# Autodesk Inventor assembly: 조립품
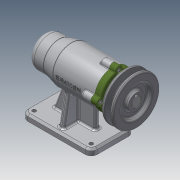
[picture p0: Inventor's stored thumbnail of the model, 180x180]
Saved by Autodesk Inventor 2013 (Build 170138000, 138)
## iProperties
Created: 2019-07
Part Number: 조립품
Document SubType Name: Assembly
Designer: user
Author: user
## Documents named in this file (12)
- C:\Users\user\Desktop\490704V1025\조립품.iam
- C:\Users\user\Desktop\490704V1025\본체.ipt
- C:\Users\user\Desktop\490704V1025\V벨트풀리.ipt
- C:\Users\user\Desktop\490704V1025\멈춤나사 M3.ipt
- C:\Users\user\Desktop\490704V1025\베어링 6004.ipt
- C:\Users\user\Desktop\490704V1025\베어링 51202.ipt
- C:\Users\user\Desktop\490704V1025\볼트 M4.ipt
- C:\Users\user\Desktop\490704V1025\어댑터슬리브.ipt
- C:\Users\user\Desktop\490704V1025\오일 실.ipt
- C:\Users\user\Desktop\490704V1025\축.ipt
- C:\Users\user\Desktop\490704V1025\커버.ipt
- C:\Users\user\Desktop\490704V1025\키 5 x 5 x 16.ipt
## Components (1 placed, 1 different names)
1. V벨트풀리:1
